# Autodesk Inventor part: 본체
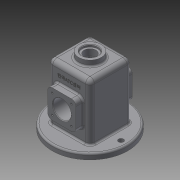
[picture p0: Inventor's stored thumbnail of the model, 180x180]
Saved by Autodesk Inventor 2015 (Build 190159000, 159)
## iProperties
Created: 2021-08
Part Number: 본체
Material: 일반
Document SubType Name: Modeling
Designer: 10415
Density: 1 g/cm^3
Appearance: 기본값
Author: 10415
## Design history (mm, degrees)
sketch "스케치1"
  geometry: C1 r 67 at (0, 0); 1 further point
  constraints: 1 centre point, 1 coincident
  dimensions: "d0" = 134 diameter of C1
extrude "돌출1" new body sketch "스케치1" distance "d1" = 10; taper "d2" = 0 deg
sketch "스케치2"
  geometry: L1 (37, -37)-(-37, -37); L2 (-37, -37)-(-37, 37); L3 (-37, 37)-(37, 37); L4 (37, 37)-(37, -37); L5 (37, -37)-(-37, 37); L6 (-37, -37)-(37, 37); C1 r 67 at (0, 0) reference
  constraints: 12 end point, 2 midpoint, 2 parallel, 1 horizontal, 1 perpendicular
  dimensions: "d3" = 74 distance of L3.end L1.start; "d4" = 74 distance of L2.end L3.end
extrude "돌출2" join sketch "스케치2" distance "d5" = 100; taper "d6" = 0 deg
sketch "스케치3"
  geometry: L1 (32, -32)-(-32, -32); L2 (-32, -32)-(-32, 32); L3 (-32, 32)-(32, 32); L4 (32, 32)-(32, -32); L5 (32, -32)-(-32, 32); L6 (-32, -32)-(32, 32); C1 r 67 at (0, 0) reference
  constraints: 12 end point, 2 midpoint, 2 parallel, 1 horizontal, 1 perpendicular
  dimensions: "d7" = 64 distance of L1.end L2.end; "d8" = 64 distance of L2.end L3.end
extrude "돌출3" cut sketch "스케치3" distance "d9" = 105; taper "d10" = 0 deg
fillet "모깎기2" dims "d27" = 3
node "작업 평면1"
sketch "스케치7"
  geometry: C1 r 20 at (0, 0); 1 further point
  constraints: 1 centre point, 1 coincident
  dimensions: "d29" = 40 diameter of C1
extrude "돌출6" join sketch "스케치7" stored distance "d30" = 13; taper "d31" = 0 deg
sketch "스케치8"
  geometry: C1 r 20 at (0, 0) reference; C2 r 14 at (0, 0)
  constraints: 1 centre point, 1 coincident
  dimensions: "d32" = 28 diameter of C2
extrude "돌출7" cut sketch "스케치8" distance "d33" = 4; taper "d34" = 0 deg
sketch "스케치9"
  geometry: C1 r 14 at (0, 0) reference; C2 r 10.5 at (0, 0)
  constraints: 1 centre point, 1 coincident
  dimensions: "d35" = 21 diameter of C2
extrude "돌출8" cut sketch "스케치9" stored distance "d36" = 4; taper "d37" = 0 deg
fillet "모깎기3" dims "d38" = 8
fillet "모깎기4" dims "d39" = 8
sketch "스케치12"
  geometry: L1 (-38, -10)-(96, -10) reference; C1 r 25 at (29, 45); 1 further point
  constraints: 1 centre point, 1 vertical alignment
  dimensions: "d56" = 50 diameter of C1; "d57" = 55 distance from line of L1 C1.centre
extrude "돌출11" join sketch "스케치12" distance "d58" = 13; taper "d60" = 0 deg; dims "d59" = 12, "d61" = 0
chamfer "모따기2" distance "d62" = 7; stored, may be unused: second distance "d63" = 2, angle "d64" = 20 deg
sketch "스케치13"
  geometry: L1 (-25, -25)-(25, -25); L2 (25, -25)-(25, 25); L3 (25, 25)-(-25, 25); L4 (-25, 25)-(-25, -25); L5 (-25, -25)-(25, 25); L6 (25, -25)-(-25, 25); C1 r 25 at (0, 0) reference; 1 further point
  constraints: 12 end point, 2 midpoint, 2 parallel, 1 horizontal, 1 perpendicular
  dimensions: "d65" = 50 distance of L2.end L3.end; "d66" = 50 distance of L1.end L2.end
extrude "돌출12" join sketch "스케치13" distance "d67" = 13; taper "d68" = 0 deg
sketch "스케치14"
  geometry: L1 (-38, -10)-(96, -10) reference; C1 r 16 at (29, 45); 1 further point
  constraints: 1 centre point, 1 vertical alignment
  dimensions: "d69" = 32 diameter of C1; "d70" = 55 distance from line of L1 C1.centre
extrude "돌출13" cut sketch "스케치14" stored distance "d71" = 13; taper "d72" = 0 deg
fillet "모깎기5" dims "d73" = 8
fillet "모깎기6" dims "d74" = 3
sketch "스케치15"
  geometry: A1 r 8 centre (12, 28) between (4, 28) and (12, 20) reference; A2 r 8 centre (46, 28) between (46, 20) and (54, 28) reference; A3 r 8 centre (46, 62) between (54, 62) and (46, 70) reference; A4 r 8 centre (12, 62) between (12, 70) and (4, 62) reference; 1 further point
hole "구멍2" sketch "스케치15" at (12, 62), (12, 28), (46, 62), (46, 28) diameter "d75" = 3.242; stored, may be unused: countersink angle "d79" = 90 deg, drill point angle "d81" = 118 deg; dims "d76" = 8, "d77" = 4, "d78" = 2, "d80" = 10
fillet "모깎기7" dims "d82" = 3
chamfer "모따기3" distance "d83" = 1; stored, may be unused: second distance "d84" = 2, angle "d85" = 20 deg
fillet "모깎기8" dims "d86" = 3
fillet "모깎기9" dims "d87" = 3
sketch "스케치16"
  geometry: C1 r 64 at (0, 0) reference; A1 r 55 centre (0, 0) between (-55, 0) and (55, 0)
  constraints: 2 point on circle, 1 centre point, 1 coincident
  dimensions: "d88" = 110 diameter of A1
hole "구멍3" sketch "스케치16" at (-55, 0), (55, 0) diameter "d89" = 9; stored, may be unused: countersink angle "d93" = 90 deg, drill point angle "d95" = 0 deg; dims "d90" = 9, "d91" = 4, "d92" = 2, "d94" = 10
fillet "모깎기10" dims "d96" = 3
chamfer "모따기4" distance "d97" = 1; stored, may be unused: second distance "d98" = 2, angle "d99" = 20 deg
sketch "스케치17"
  geometry: L1 (9, 18)-(49, 18) reference; L2 (-8, 0)-(-8, -89) reference; 2 further points
  constraints: 1 other
  dimensions: "d100" = 28 distance from line of point (29, -10) L1; "d101" = 37 distance from line of L2 point (29, -10)
feature "엠보싱1" sketch "스케치17" dims "d7" = 64, "d8" = 64, "d102" = 0.5, "d103" = 0
node "솔리드1"
mirror "대칭2"
mirror "대칭3"
